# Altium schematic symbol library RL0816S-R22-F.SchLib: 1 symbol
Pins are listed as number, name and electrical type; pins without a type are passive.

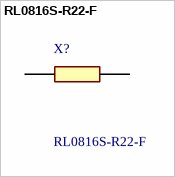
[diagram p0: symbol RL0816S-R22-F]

## RL0816S-R22-F
designator X?
220 mOhms +/-1% 0.2W, 1/5W Chip Resistor 0603 (1608 Metric) Current Sense Thin Film; Manufacturer_Name: Susumu; Geometry.Height: 0.55mm
footprint RESC1608X55N
pins: 1, 2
